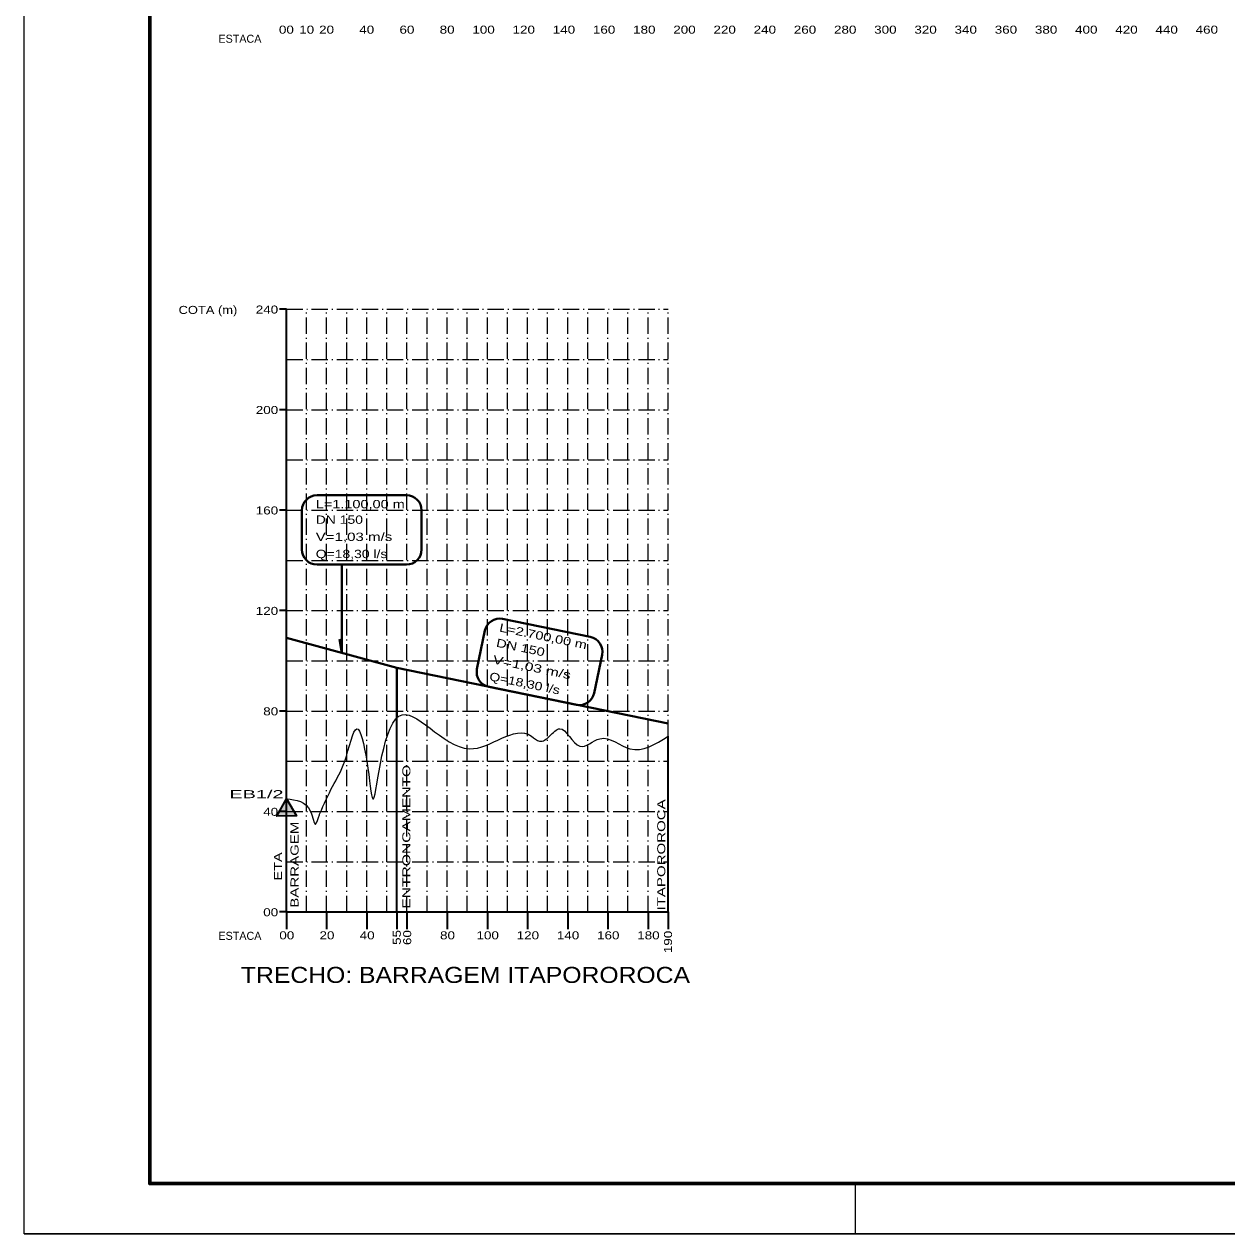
# Model space of a CAD drawing. Extents: x 0 to 1772, y 0 to 1188.
# Drawn here: x -0.2 to 478.7, y -0.1 to 481.5 of the extents above; entities that cross this region are included whole.
import ezdxf
from ezdxf.enums import TextEntityAlignment as Align

# ---------------------------------------------------------------- set-up
doc = ezdxf.new("R2010")
doc.units = 0
doc.header["$LTSCALE"] = 1.3
doc.linetypes.add('DOT_DASHED', pattern=[7.7, 5, -1.2, 0.3, -1.2])
for name, color, linetype, lineweight in [('1', 7, 'DOT_DASHED', 13), ('24', 7, 'Continuous', 35), ('56', 7, 'Continuous', 13), ('62', 7, 'Continuous', 13), ('63', 7, 'Continuous', 25), ('9', 7, 'Continuous', 40)]:
    doc.layers.add(name, color=color, linetype=linetype, lineweight=lineweight)

msp = doc.modelspace()

# ---------------------------------------------------------------- hatches: boundary and pattern name
at = {"layer": '62'}
msp.add_hatch(color=256, dxfattribs=at).paths.add_polyline_path([(104.257, 173.02), (108.203, 166.282), (100.395, 166.233)])

# ---------------------------------------------------------------- linework, layer by layer
at = {"layer": '1'}
for p, q in [((104.257, 368.02), (256.257, 368.02)), ((112.257, 128.02), (112.257, 368.02)), ((120.257, 128.02), (120.257, 368.02)), ((128.257, 128.02), (128.257, 368.02)), ((136.257, 128.02), (136.257, 368.02)), ((144.257, 128.02), (144.257, 368.02)), ((152.257, 128.02), (152.257, 368.02)), ((160.257, 128.02), (160.257, 368.02)), ((168.257, 128.02), (168.257, 368.02)), ((176.257, 128.02), (176.257, 368.02)), ((184.257, 128.02), (184.257, 368.02)), ((192.257, 128.02), (192.257, 368.02)), ((200.257, 128.02), (200.257, 368.02)), ((208.257, 128.02), (208.257, 368.02)), ((216.257, 128.02), (216.257, 368.02)), ((224.257, 128.02), (224.257, 368.02)), ((232.257, 128.02), (232.257, 368.02)), ((240.257, 128.02), (240.257, 368.02)), ((248.257, 128.02), (248.257, 368.02)), ((256.257, 128.02), (256.257, 368.02)), ((104.257, 348.02), (256.257, 348.02)), ((104.257, 328.02), (256.257, 328.02)), ((104.257, 308.02), (256.257, 308.02)), ((104.257, 288.02), (256.257, 288.02)), ((104.257, 268.02), (256.257, 268.02)), ((104.257, 248.02), (256.257, 248.02)), ((104.257, 228.02), (256.257, 228.02)), ((104.257, 208.02), (256.257, 208.02)), ((104.257, 188.02), (256.257, 188.02)), ((104.257, 168.02), (256.257, 168.02)), ((104.257, 148.02), (256.257, 148.02))]:
    msp.add_line(p, q, dxfattribs=at)
at = {"layer": '56'}
for points in [[(117.526, 167.228), (122.657, 178.02), (127.457, 188.02), (132.257, 201.02), (136.257, 188.02), (138.657, 173.02), (149.057, 206.02), (177.057, 193.02), (201.857, 198.02), (205.057, 196.02), (209.057, 198.02), (213.057, 201.02), (221.057, 194.02), (229.057, 197.02), (241.057, 193.02), (256.261, 197.983)], [(104.257, 173.02), (113.857, 168.02), (115.857, 163.02), (117.357, 166.77), (117.526, 167.228)]]:
    msp.add_spline(points, degree=3, dxfattribs=at)
at = {"layer": '62', "lineweight": 35}
for p, q in [((104.257, 368.02), (101.526, 368.02)), ((104.089, 368.02), (104.257, 368.02)), ((104.257, 128.02), (104.257, 368.02)), ((104.089, 358.02), (104.257, 358.02)), ((104.089, 348.02), (104.257, 348.02)), ((104.089, 338.02), (104.257, 338.02)), ((104.257, 328.02), (101.526, 328.02)), ((104.089, 328.02), (104.257, 328.02)), ((104.089, 318.02), (104.257, 318.02)), ((104.089, 308.02), (104.257, 308.02)), ((104.089, 298.02), (104.257, 298.02)), ((104.257, 288.02), (101.526, 288.02)), ((104.089, 288.02), (104.257, 288.02)), ((104.089, 278.02), (104.257, 278.02)), ((104.089, 268.02), (104.257, 268.02)), ((104.089, 258.02), (104.257, 258.02)), ((104.257, 248.02), (101.526, 248.02)), ((104.089, 248.02), (104.257, 248.02)), ((104.089, 238.02), (104.257, 238.02)), ((104.089, 228.02), (104.257, 228.02)), ((104.089, 218.02), (104.257, 218.02)), ((104.257, 208.02), (101.526, 208.02)), ((104.089, 208.02), (104.257, 208.02)), ((148.257, 128.02), (148.257, 205.969)), ((104.089, 198.02), (104.257, 198.02)), ((256.257, 128.02), (256.257, 197.983)), ((104.089, 188.02), (104.257, 188.02)), ((104.089, 178.02), (104.257, 178.02)), ((104.257, 168.02), (101.526, 168.02)), ((104.089, 168.02), (104.257, 168.02)), ((104.089, 158.02), (104.257, 158.02)), ((104.089, 148.02), (104.257, 148.02)), ((104.089, 138.02), (104.257, 138.02)), ((104.257, 128.02), (101.526, 128.02)), ((104.257, 128.02), (104.257, 121.193)), ((104.257, 128.02), (256.257, 128.02)), ((120.257, 128.02), (120.257, 121.193)), ((136.257, 128.02), (136.257, 121.193)), ((148.257, 128.02), (148.257, 121.193)), ((152.257, 128.02), (152.257, 121.193)), ((168.257, 128.02), (168.257, 121.193)), ((184.257, 128.02), (184.257, 121.193)), ((200.257, 128.02), (200.257, 121.193)), ((216.257, 128.02), (216.257, 121.193)), ((232.257, 128.02), (232.257, 121.193)), ((248.257, 128.02), (248.257, 121.193)), ((256.257, 128.02), (256.257, 121.193))]:
    msp.add_line(p, q, dxfattribs=at)
at = {"layer": '62'}
for p, q in [((104.089, 366.02), (104.257, 366.02)), ((104.089, 364.02), (104.257, 364.02)), ((104.089, 362.02), (104.257, 362.02)), ((104.089, 360.02), (104.257, 360.02)), ((104.089, 356.02), (104.257, 356.02)), ((104.089, 354.02), (104.257, 354.02)), ((104.089, 352.02), (104.257, 352.02)), ((104.089, 350.02), (104.257, 350.02)), ((104.089, 346.02), (104.257, 346.02)), ((104.089, 344.02), (104.257, 344.02)), ((104.089, 342.02), (104.257, 342.02)), ((104.089, 340.02), (104.257, 340.02)), ((104.089, 336.02), (104.257, 336.02)), ((104.089, 334.02), (104.257, 334.02)), ((104.089, 332.02), (104.257, 332.02)), ((104.089, 330.02), (104.257, 330.02)), ((104.089, 326.02), (104.257, 326.02)), ((104.089, 324.02), (104.257, 324.02)), ((104.089, 322.02), (104.257, 322.02)), ((104.089, 320.02), (104.257, 320.02)), ((104.089, 316.02), (104.257, 316.02)), ((104.089, 314.02), (104.257, 314.02)), ((104.089, 312.02), (104.257, 312.02)), ((104.089, 310.02), (104.257, 310.02)), ((104.089, 306.02), (104.257, 306.02)), ((104.089, 304.02), (104.257, 304.02)), ((104.089, 302.02), (104.257, 302.02)), ((104.089, 300.02), (104.257, 300.02)), ((104.089, 296.02), (104.257, 296.02)), ((104.089, 294.02), (104.257, 294.02)), ((104.089, 292.02), (104.257, 292.02)), ((104.089, 290.02), (104.257, 290.02)), ((104.089, 286.02), (104.257, 286.02)), ((104.089, 284.02), (104.257, 284.02)), ((104.089, 282.02), (104.257, 282.02)), ((104.089, 280.02), (104.257, 280.02)), ((104.089, 276.02), (104.257, 276.02)), ((104.089, 274.02), (104.257, 274.02)), ((104.089, 272.02), (104.257, 272.02)), ((104.089, 270.02), (104.257, 270.02)), ((104.089, 266.02), (104.257, 266.02)), ((104.089, 264.02), (104.257, 264.02)), ((104.089, 262.02), (104.257, 262.02)), ((104.089, 260.02), (104.257, 260.02)), ((104.089, 256.02), (104.257, 256.02)), ((104.089, 254.02), (104.257, 254.02)), ((104.089, 252.02), (104.257, 252.02)), ((104.089, 250.02), (104.257, 250.02)), ((104.089, 246.02), (104.257, 246.02)), ((104.089, 244.02), (104.257, 244.02)), ((104.089, 242.02), (104.257, 242.02)), ((104.089, 240.02), (104.257, 240.02)), ((104.089, 236.02), (104.257, 236.02)), ((104.089, 234.02), (104.257, 234.02)), ((104.089, 232.02), (104.257, 232.02)), ((104.089, 230.02), (104.257, 230.02)), ((104.089, 226.02), (104.257, 226.02)), ((104.089, 224.02), (104.257, 224.02)), ((104.089, 222.02), (104.257, 222.02)), ((104.089, 220.02), (104.257, 220.02)), ((104.089, 216.02), (104.257, 216.02)), ((104.089, 214.02), (104.257, 214.02)), ((104.089, 212.02), (104.257, 212.02)), ((104.089, 210.02), (104.257, 210.02)), ((104.089, 206.02), (104.257, 206.02)), ((104.089, 204.02), (104.257, 204.02)), ((104.089, 202.02), (104.257, 202.02)), ((104.089, 200.02), (104.257, 200.02)), ((104.089, 196.02), (104.257, 196.02)), ((104.089, 194.02), (104.257, 194.02)), ((104.089, 192.02), (104.257, 192.02)), ((104.089, 190.02), (104.257, 190.02)), ((104.089, 186.02), (104.257, 186.02)), ((104.089, 184.02), (104.257, 184.02)), ((104.089, 182.02), (104.257, 182.02)), ((104.089, 180.02), (104.257, 180.02)), ((104.089, 176.02), (104.257, 176.02)), ((104.089, 174.02), (104.257, 174.02)), ((104.089, 172.02), (104.257, 172.02)), ((104.089, 170.02), (104.257, 170.02)), ((104.089, 166.02), (104.257, 166.02)), ((104.089, 164.02), (104.257, 164.02)), ((104.089, 162.02), (104.257, 162.02)), ((104.089, 160.02), (104.257, 160.02)), ((104.089, 156.02), (104.257, 156.02)), ((104.089, 154.02), (104.257, 154.02)), ((104.089, 152.02), (104.257, 152.02)), ((104.089, 150.02), (104.257, 150.02)), ((104.089, 146.02), (104.257, 146.02)), ((104.089, 144.02), (104.257, 144.02)), ((104.089, 142.02), (104.257, 142.02)), ((104.089, 140.02), (104.257, 140.02)), ((104.089, 136.02), (104.257, 136.02)), ((104.089, 134.02), (104.257, 134.02)), ((104.089, 132.02), (104.257, 132.02)), ((104.089, 130.02), (104.257, 130.02))]:
    msp.add_line(p, q, dxfattribs=at)
at = {"layer": '62', "lineweight": 35}
msp.add_lwpolyline([(104.257, 173.02), (108.203, 166.282), (100.395, 166.233)], close=True, dxfattribs=at)
at = {"layer": '63'}
for p, q in [((-0.167, -0.127), (-0.167, 1187.873)), ((330.833, -0.127), (330.833, 19.873))]:
    msp.add_line(p, q, dxfattribs=at)
for points in [[(-0.167, -0.127), (1771.833, -0.127), (1771.833, 1187.873)], [(-0.167, -0.127), (1771.833, -0.127), (-0.167, -0.127)]]:
    msp.add_lwpolyline(points, dxfattribs=at)
at = {"layer": '63', "lineweight": 60}
msp.add_lwpolyline([(49.833, 1167.873), (1751.833, 1167.873), (1751.833, 19.873), (49.833, 19.873)], close=True, dxfattribs=at)
at = {"layer": '9'}
for p, q in [((116.44, 293.956), (152.074, 293.956)), ((110.44, 287.956), (110.44, 272.345)), ((158.074, 287.956), (158.074, 272.345)), ((116.44, 266.345), (152.074, 266.345)), ((190.356, 244.734), (225.262, 237.569)), ((183.272, 240.063), (180.133, 224.772)), ((229.933, 230.485), (226.794, 215.193)), ((148.257, 205.969), (148.257, 225.19)), ((184.804, 217.688), (219.71, 210.522))]:
    msp.add_line(p, q, dxfattribs=at)
for points in [[(125.426, 236.645), (126.257, 231.21), (126.257, 266.345)], [(104.257, 237.23), (148.257, 225.19), (256.257, 203.02)]]:
    msp.add_lwpolyline(points, dxfattribs=at)
for centre, start, end in [((116.44, 287.956), 90, 180), ((152.074, 287.956), 0, 90), ((116.44, 272.345), 180, 270), ((152.074, 272.345), 270, 0), ((189.15, 238.857), 78.3996, 168.3996), ((224.056, 231.691), 348.3996, 78.3996), ((186.011, 223.565), 168.3996, 258.3996), ((220.917, 216.4), 258.3996, 348.3996)]:
    msp.add_arc(centre, 6, start, end, dxfattribs=at)

# ---------------------------------------------------------------- texts
at = {"layer": '24'}
for p in [(85.732, 474.163), (85.732, 116.932)]:
    msp.add_text('ESTACA', height=3.2, dxfattribs=at).set_placement(p, align=Align.CENTER)
for s, width, p in [('00', 1.25, (107.214, 477.773)), ('10', 1.25, (115.296, 477.773)), ('20', 1.25, (123.214, 477.773)), ('40', 1.25, (139.214, 477.773)), ('60', 1.25, (155.214, 477.773)), ('80', 1.25, (171.214, 477.773)), ('100', 1.25, (187.214, 477.773)), ('120', 1.25, (203.214, 477.773)), ('140', 1.25, (219.214, 477.773)), ('160', 1.25, (235.214, 477.773)), ('180', 1.25, (251.214, 477.773)), ('200', 1.25, (267.214, 477.773)), ('220', 1.25, (283.214, 477.773)), ('240', 1.25, (299.214, 477.773)), ('260', 1.25, (315.214, 477.773)), ('280', 1.25, (331.214, 477.773)), ('300', 1.25, (347.214, 477.773)), ('320', 1.25, (363.214, 477.773)), ('340', 1.25, (379.214, 477.773)), ('360', 1.25, (395.214, 477.773)), ('380', 1.25, (411.214, 477.773)), ('400', 1.25, (427.214, 477.773)), ('420', 1.25, (443.214, 477.773)), ('440', 1.25, (459.214, 477.773)), ('460', 1.25, (475.214, 477.773)), ('COTA (m)', 1.2, (84.696, 366.164)), ('240', 1.25, (100.969, 366.319)), ('200', 1.25, (100.969, 326.319)), ('160', 1.25, (100.969, 286.319)), ('120', 1.25, (100.969, 246.319)), ('80', 1.25, (100.969, 206.319)), ('40', 1.25, (100.969, 166.319)), ('00', 1.25, (100.969, 126.319))]:
    msp.add_text(s, height=3.2, dxfattribs=dict(at, width=width)).set_placement(p, align=Align.RIGHT)
for s, width, p in [('ENTRONCAMENTO', 1.45, (153.61, 129.365)), ('ITAPOROROCA', 1.4, (255.112, 128.616)), ('BARRAGEM', 1.4, (109.075, 129.721)), ('ETA', 1.35, (102.495, 140.537))]:
    msp.add_text(s, height=3.2, rotation=90, dxfattribs=dict(at, width=width)).set_placement(p)
at = {"layer": '24', "width": 1.85}
msp.add_text('EB1/2', height=3.2, dxfattribs=at).set_placement((81.537, 173.34))
at = {"layer": '24', "width": 1.25}
for s, p in [('55', (149.793, 117.892)), ('60', (153.946, 117.83)), ('190', (257.797, 116.092))]:
    msp.add_text(s, height=3.2, rotation=90, dxfattribs=at).set_placement(p, align=Align.CENTER)
at = {"layer": '24'}
for s, height, width, p in [('00', 3.2, 1.25, (104.397, 117.129)), ('20', 3.2, 1.25, (120.397, 117.129)), ('40', 3.2, 1.25, (136.397, 117.129)), ('80', 3.2, 1.25, (168.397, 117.129)), ('100', 3.2, 1.25, (184.397, 117.129)), ('120', 3.2, 1.25, (200.397, 117.129)), ('140', 3.2, 1.25, (216.397, 117.129)), ('160', 3.2, 1.25, (232.397, 117.129)), ('180', 3.2, 1.25, (248.397, 117.129)), ('TRECHO: BARRAGEM ITAPOROROCA', 6.4, 1.15, (175.545, 99.77))]:
    msp.add_text(s, height=height, dxfattribs=dict(at, width=width)).set_placement(p, align=Align.CENTER)
at = {"layer": '9'}
for s, width, p in [('L=1.100,00 m', 1.3, (115.925, 288.777)), ('DN 150', 1.25, (115.925, 282.597)), ('V=1,03 m/s', 1.35, (115.925, 275.774)), ('Q=18,30 l/s', 1.25, (115.925, 268.95))]:
    msp.add_text(s, height=3.319, dxfattribs=dict(at, width=width)).set_placement(p)
for s, width, p in [('L=2.700,00 m', 1.3, (188.81, 239.765)), ('DN 150', 1.3, (187.568, 233.711)), ('V=1,03 m/s', 1.4, (186.195, 227.027)), ('Q=18,30 l/s', 1.25, (184.823, 220.343))]:
    msp.add_text(s, height=3.319, rotation=348.4, dxfattribs=dict(at, width=width)).set_placement(p)

doc.saveas('drawing.dxf')
